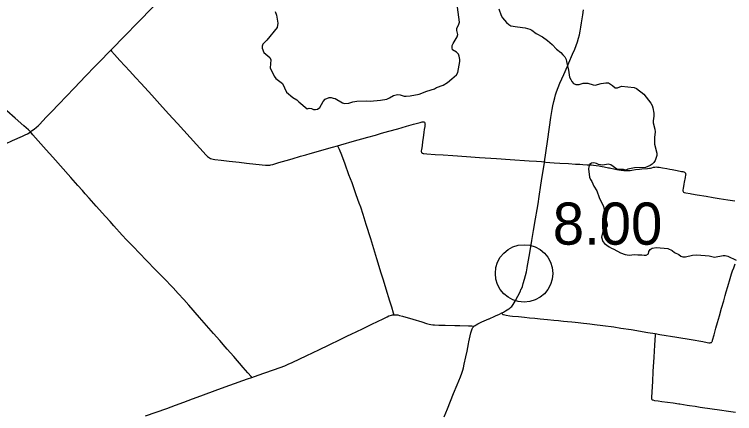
# Model space of a CAD drawing. Extents: x 1597222 to 1925846, y 496284 to 911751.
# Drawn here: x 1678855 to 1697673, y 536551 to 546977 of the extents above; entities that cross this region are included whole.
import ezdxf

# ---------------------------------------------------------------- set-up
doc = ezdxf.new("R2010")
doc.units = 0
for name, color, linetype in [('Default', 7, 'Continuous'), ('GM_X_County_Road', 7, 'Continuous'), ('GM_X_Township', 7, 'Continuous'), ('GM_X_Township_Road', 7, 'Continuous'), ('GM_X_US_Route', 7, 'Continuous')]:
    doc.layers.add(name, color=color, linetype=linetype)

msp = doc.modelspace()

# ---------------------------------------------------------------- linework, layer by layer
at = {"layer": 'Default'}
msp.add_circle((1692172, 540213), 750, dxfattribs=at)
msp.add_circle((1692172, 540213), 750, dxfattribs=at)
at = {"layer": 'GM_X_County_Road'}
for points in [[(1681373, 546046), (1681485, 546161), (1681647, 546324), (1681854, 546534), (1681969, 546651), (1682165, 546850), (1682394, 547084), (1682544, 547236), (1682671, 547364), (1682843, 547540), (1682923, 547622), (1683085, 547785), (1683190, 547889), (1683226, 547921), (1683252, 547941), (1683272, 547953), (1683291, 547962), (1683306, 547968), (1683322, 547972)], [(1679273, 543912), (1679306, 543934), (1679371, 543984), (1679435, 544036), (1679472, 544068), (1679507, 544103), (1679599, 544197), (1679689, 544292), (1679826, 544434), (1680019, 544635), (1680415, 545050), (1680722, 545370), (1680960, 545619), (1681153, 545820), (1681279, 545949), (1681373, 546046)], [(1675533, 542090), (1675880, 542286), (1676194, 542464), (1676435, 542603), (1676521, 542651), (1676594, 542688), (1676698, 542737), (1676982, 542865), (1677147, 542938), (1677312, 543011), (1677611, 543146), (1677776, 543218), (1677911, 543279), (1678060, 543347), (1678240, 543426), (1678435, 543514), (1678809, 543682), (1679063, 543796), (1679138, 543831), (1679196, 543862), (1679238, 543887), (1679273, 543912)], [(1685059, 537497), (1685223, 537555), (1685796, 537756), (1685918, 537802), (1686009, 537840), (1686114, 537886), (1686499, 538069), (1686647, 538140), (1686824, 538225), (1687060, 538340), (1687386, 538495), (1687563, 538582), (1687651, 538625), (1687947, 538767), (1688198, 538887), (1688493, 539030), (1688597, 539081), (1688642, 539100), (1688673, 539111), (1688705, 539120), (1688738, 539127), (1688771, 539131)], [(1688771, 539131), (1688804, 539132), (1688837, 539130), (1688870, 539126), (1688918, 539116), (1688998, 539094), (1689265, 539014), (1689501, 538945), (1689626, 538906), (1689690, 538890), (1689737, 538879), (1689785, 538872), (1689834, 538868), (1689949, 538864), (1690113, 538860), (1690359, 538853), (1690490, 538850), (1690719, 538845), (1690791, 538843), (1690806, 538841)], [(1690806, 538841), (1690844, 538837), (1690855, 538834), (1690865, 538832)], [(1682278, 536489), (1682556, 536588), (1682834, 536687), (1683065, 536771), (1683281, 536851), (1683512, 536935), (1683728, 537013), (1684175, 537176), (1684483, 537289), (1684945, 537457), (1685059, 537497)]]:
    msp.add_lwpolyline(points, dxfattribs=at)
at = {"layer": 'GM_X_Township'}
for points in [[(1685671, 547050), (1685704, 546958), (1685738, 546753), (1685717, 546633), (1685453, 546309), (1685348, 546204), (1685329, 546152), (1685327, 546100), (1685372, 545986), (1685531, 545848), (1685556, 545795), (1685540, 545585), (1685644, 545368), (1685684, 545307), (1685857, 545169), (1685969, 544946), (1686130, 544810), (1686239, 544747), (1686283, 544696), (1686507, 544515), (1686560, 544531), (1686620, 544524), (1686673, 544495), (1686723, 544491), (1686774, 544504), (1686838, 544547), (1686924, 544704), (1686975, 544764), (1687078, 544805), (1687130, 544810), (1687188, 544793), (1687240, 544777), (1687427, 544664), (1687481, 544647), (1687595, 544656), (1687700, 544693), (1687806, 544709), (1688043, 544720), (1688155, 544709), (1688420, 544734), (1688586, 544766), (1688653, 544795), (1688758, 544862), (1688869, 544888), (1688933, 544880), (1689040, 544842), (1689092, 544839), (1689195, 544850), (1689430, 544897), (1689631, 544975), (1689830, 545037), (1689887, 545066), (1690060, 545132), (1690169, 545201), (1690288, 545291), (1690408, 545400), (1690443, 545460), (1690492, 545748), (1690495, 545804), (1690480, 545888), (1690461, 545940), (1690407, 545995), (1690302, 546050), (1690290, 546101), (1690297, 546165), (1690316, 546219), (1690422, 546390), (1690443, 546449), (1690414, 546558), (1690417, 546612), (1690470, 546719), (1690483, 546771), (1690434, 547171)], [(1691516, 547119), (1691572, 546950), (1691609, 546886), (1691717, 546762), (1691775, 546713), (1691829, 546680), (1692003, 546650), (1692197, 546628), (1692319, 546594), (1692376, 546565), (1692490, 546482), (1692653, 546396), (1692782, 546296), (1692903, 546188), (1693017, 546068), (1693129, 545983), (1693188, 545922), (1693235, 545865), (1693269, 545803), (1693280, 545750), (1693329, 545524), (1693359, 545335), (1693394, 545276), (1693420, 545224), (1693465, 545173), (1693521, 545151), (1693611, 545143), (1693661, 545167), (1693714, 545178), (1693838, 545179), (1693976, 545135), (1694028, 545126), (1694191, 545172), (1694313, 545189), (1694375, 545186), (1694485, 545120), (1694552, 545061), (1694610, 545063), (1694715, 545103), (1695045, 545071), (1695109, 545046), (1695299, 544894), (1695483, 544659), (1695518, 544599), (1695541, 544536), (1695566, 544402), (1695565, 544321), (1695543, 544198), (1695542, 544147), (1695586, 543977), (1695594, 543912), (1695580, 543758), (1695584, 543588), (1695645, 543349), (1695642, 543289), (1695598, 543165), (1695566, 543113), (1695519, 543062), (1695464, 543028), (1695344, 542982), (1695059, 542971), (1694886, 542932), (1694832, 542908), (1694774, 542925), (1694652, 542928), (1694600, 542937), (1694441, 543045), (1694379, 543070), (1694224, 543044), (1694116, 543059), (1694064, 543084), (1693994, 543103), (1693936, 543092), (1693884, 543056), (1693870, 543016), (1693865, 543000), (1693858, 542944), (1693880, 542730), (1693905, 542667), (1693940, 542613), (1693999, 542490), (1694071, 542371), (1694131, 542194), (1694245, 541960), (1694271, 541839), (1694280, 541733), (1694345, 541496), (1694342, 541446), (1694314, 541394), (1694261, 541333), (1694224, 541275), (1694193, 541163), (1694233, 541042), (1694277, 540990), (1694396, 540904), (1694454, 540871), (1694521, 540848), (1694694, 540746), (1694810, 540705), (1694868, 540698), (1694930, 540693), (1695045, 540704), (1695147, 540696), (1695251, 540701), (1695309, 540690), (1695365, 540692), (1695420, 540727), (1695436, 540787), (1695471, 540839), (1695522, 540868), (1695636, 540885), (1695928, 540865), (1696046, 540809), (1696105, 540762), (1696213, 540703), (1696269, 540662), (1696324, 540646), (1696391, 540647), (1696573, 540690), (1696684, 540695), (1697012, 540669), (1697152, 540639), (1697373, 540676), (1697431, 540678), (1697493, 540661), (1697710, 540557)]]:
    msp.add_lwpolyline(points, dxfattribs=at)
at = {"layer": 'GM_X_Township_Road'}
for points in [[(1681373, 546046), (1681395, 546020), (1681470, 545934), (1681613, 545776), (1681868, 545498), (1682023, 545329), (1682168, 545172), (1682442, 544868), (1682652, 544637), (1682883, 544383), (1683115, 544128), (1683446, 543764), (1683864, 543302), (1683899, 543267), (1683924, 543247), (1683952, 543230), (1683982, 543216), (1684013, 543206), (1684045, 543198), (1684094, 543191), (1684257, 543173), (1684468, 543148), (1684729, 543116), (1684924, 543093), (1685331, 543045), (1685413, 543038), (1685462, 543036), (1685494, 543037), (1685527, 543041), (1685559, 543047), (1685607, 543059), (1685764, 543105), (1685953, 543161), (1686110, 543207), (1686331, 543271), (1686472, 543312), (1686583, 543344), (1686866, 543425), (1687071, 543483), (1687166, 543510), (1687301, 543542)], [(1679273, 543912), (1679246, 543938), (1679222, 543961), (1679099, 544070), (1678879, 544266), (1678657, 544461)], [(1687301, 543542), (1687387, 543568), (1687740, 543672), (1687930, 543725), (1688087, 543770), (1688293, 543827), (1688451, 543872), (1688640, 543924), (1688877, 543992), (1689098, 544054), (1689287, 544109), (1689461, 544158), (1689509, 544172), (1689525, 544174), (1689541, 544173), (1689556, 544168), (1689569, 544159), (1689578, 544146), (1689583, 544130), (1689584, 544114), (1689583, 544097), (1689576, 544048), (1689565, 543967), (1689556, 543902), (1689536, 543756), (1689522, 543658), (1689506, 543545), (1689490, 543447), (1689486, 543415), (1689486, 543398), (1689489, 543382), (1689496, 543368), (1689507, 543356), (1689521, 543349), (1689537, 543344), (1689554, 543342), (1689635, 543336), (1689848, 543321), (1690061, 543308), (1690307, 543292), (1690667, 543267), (1691010, 543244), (1691452, 543215), (1691812, 543189), (1692303, 543156), (1692500, 543143), (1692631, 543133), (1692696, 543126), (1692705, 543125)], [(1680706, 542295), (1680634, 542376), (1680515, 542512), (1680330, 542720), (1679862, 543248), (1679687, 543444), (1679480, 543677), (1679338, 543836), (1679273, 543912)], [(1687301, 543542), (1687343, 543455), (1687400, 543306), (1687486, 543076), (1687589, 542799), (1687668, 542584), (1687780, 542276), (1687858, 542060), (1687896, 541951), (1687957, 541764), (1688040, 541498), (1688156, 541122), (1688317, 540606), (1688434, 540230), (1688492, 540042), (1688564, 539807), (1688660, 539494), (1688707, 539337), (1688756, 539180), (1688771, 539131)], [(1692705, 543125), (1692744, 543118), (1692842, 543108), (1692956, 543100), (1693104, 543092), (1693333, 543080), (1693513, 543070), (1693627, 543063), (1693709, 543058), (1693824, 543052), (1693885, 543050)], [(1693885, 543050), (1693938, 543047), (1693987, 543043), (1694052, 543034), (1694133, 543019), (1694165, 543014), (1694214, 543006), (1694262, 542996), (1694375, 542973), (1694407, 542967), (1694439, 542960), (1694599, 542925), (1694648, 542917), (1694713, 542909), (1694778, 542903), (1694844, 542900), (1694893, 542901), (1694942, 542904), (1694991, 542909), (1695088, 542923), (1695185, 542937), (1695251, 542944), (1695398, 542952), (1695447, 542957), (1695479, 542964), (1695511, 542972), (1695558, 542985), (1695591, 542990), (1695623, 542992), (1695656, 542991), (1695705, 542986), (1695786, 542973), (1695899, 542953), (1695979, 542938), (1696044, 542925), (1696172, 542900), (1696285, 542878), (1696317, 542871), (1696349, 542863), (1696364, 542856), (1696377, 542847), (1696387, 542834), (1696393, 542819), (1696395, 542803), (1696394, 542786), (1696383, 542721), (1696359, 542592), (1696350, 542544), (1696328, 542431), (1696323, 542398), (1696322, 542382), (1696323, 542366), (1696329, 542351), (1696339, 542338), (1696352, 542329), (1696367, 542322), (1696399, 542314), (1696512, 542296), (1696545, 542290), (1696691, 542267), (1696933, 542226), (1697111, 542198), (1697273, 542171), (1697500, 542134), (1697678, 542104)], [(1685059, 537497), (1685040, 537519), (1684953, 537618), (1684835, 537754), (1684588, 538039), (1684415, 538236), (1684361, 538298), (1684221, 538459), (1684059, 538644), (1683875, 538853), (1683694, 539065), (1683414, 539387), (1683283, 539534), (1683138, 539690), (1683003, 539833), (1682753, 540094), (1682571, 540282), (1682285, 540576), (1682148, 540717), (1681929, 540939), (1681781, 541093), (1681670, 541213), (1681454, 541459), (1681355, 541569), (1681234, 541703), (1680995, 541973), (1680809, 542181), (1680706, 542295)], [(1695601, 538642), (1695718, 538621), (1696163, 538543), (1696535, 538483), (1696843, 538431), (1696955, 538410), (1697004, 538402), (1697021, 538401), (1697037, 538402), (1697053, 538405), (1697067, 538412), (1697079, 538423), (1697088, 538437), (1697094, 538452), (1697099, 538468), (1697138, 538610), (1697186, 538784), (1697226, 538926), (1697275, 539100), (1697334, 539304), (1697389, 539493), (1697430, 539635), (1697456, 539730), (1697496, 539872), (1697555, 540076), (1697593, 540202), (1697620, 540279), (1697649, 540356), (1697692, 540462)], [(1691587, 539179), (1691599, 539159), (1691603, 539154), (1691608, 539149), (1691614, 539146), (1691621, 539143), (1691669, 539127), (1691701, 539120), (1691797, 539104), (1691874, 539097), (1692025, 539083), (1692187, 539066), (1692318, 539056), (1692452, 539042), (1692595, 539029), (1692781, 539009), (1692950, 538991), (1693069, 538978), (1693135, 538972), (1693204, 538965), (1693304, 538956), (1693419, 538945), (1693505, 538937), (1693589, 538929), (1693723, 538915), (1693816, 538906), (1693891, 538898), (1694016, 538881), (1694228, 538854), (1694519, 538815), (1694701, 538786), (1694971, 538744), (1695405, 538673), (1695463, 538664), (1695537, 538652), (1695601, 538642)], [(1695601, 538642), (1695597, 538602), (1695580, 538339), (1695562, 538028), (1695541, 537652), (1695528, 537390), (1695521, 537259), (1695511, 537111), (1695501, 536980), (1695500, 536948), (1695502, 536933), (1695508, 536919), (1695519, 536911), (1695533, 536906), (1695581, 536895), (1695678, 536882), (1695775, 536868), (1696068, 536828), (1696214, 536807), (1696246, 536802), (1696433, 536772), (1696498, 536763), (1696643, 536741), (1696772, 536722), (1697338, 536641), (1697451, 536625), (1697694, 536591)]]:
    msp.add_lwpolyline(points, dxfattribs=at)
at = {"layer": 'GM_X_US_Route'}
for points in [[(1693705, 546968), (1693722, 547096)], [(1692782, 543658), (1692791, 543717), (1692873, 544286), (1692906, 544496), (1692924, 544593), (1692949, 544705), (1692973, 544800), (1692996, 544879), (1693022, 544956), (1693062, 545064), (1693111, 545185), (1693210, 545411), (1693307, 545629), (1693343, 545710), (1693441, 545936), (1693498, 546072), (1693533, 546165), (1693565, 546258), (1693593, 546353), (1693618, 546448), (1693640, 546544), (1693658, 546641), (1693676, 546755), (1693705, 546968)], [(1692256, 540360), (1692257, 540364), (1692323, 540752), (1692378, 541075), (1692421, 541334), (1692474, 541642), (1692513, 541885), (1692538, 542030), (1692569, 542225), (1692613, 542517), (1692649, 542744), (1692702, 543101), (1692705, 543125), (1692782, 543658)], [(1690427, 537306), (1690510, 537513), (1690545, 537605), (1690571, 537683), (1690588, 537747), (1690611, 537843), (1690653, 538035), (1690684, 538179), (1690723, 538372), (1690733, 538423), (1690765, 538582), (1690782, 538662), (1690795, 538709), (1690805, 538739), (1690819, 538769), (1690827, 538783), (1690835, 538796), (1690844, 538810), (1690854, 538821), (1690865, 538832), (1690875, 538841), (1690891, 538854), (1690918, 538871), (1690961, 538894), (1691036, 538928), (1691071, 538944), (1691255, 539028), (1691260, 539030), (1691408, 539097), (1691425, 539103), (1691529, 539151), (1691587, 539179), (1691632, 539202), (1691691, 539233), (1691733, 539259), (1691774, 539286), (1691801, 539305), (1691826, 539327), (1691849, 539351), (1691870, 539376), (1691890, 539403), (1691917, 539444), (1691941, 539487), (1692010, 539618), (1692076, 539751), (1692092, 539788), (1692103, 539811), (1692127, 539872), (1692153, 539950), (1692187, 540060), (1692213, 540155), (1692235, 540251), (1692256, 540360)], [(1690083, 536464), (1690171, 536677), (1690332, 537072), (1690425, 537300), (1690427, 537306)]]:
    msp.add_lwpolyline(points, dxfattribs=at)

# ---------------------------------------------------------------- texts
at = {"layer": 'Default'}
msp.add_text('8.00', height=1100, dxfattribs=at).set_placement((1692922, 540963))
msp.add_text('8.00', height=1100, dxfattribs=at).set_placement((1692922, 540963))

doc.saveas('drawing.dxf')
